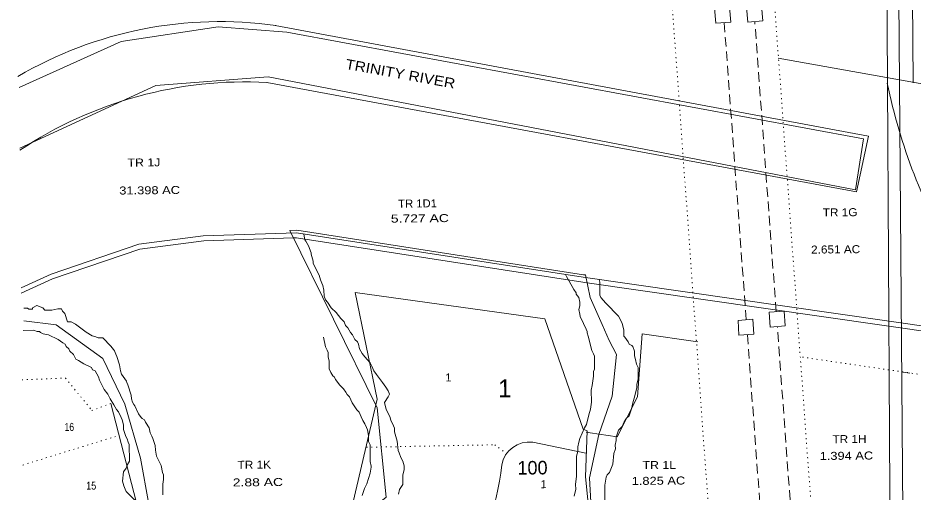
# Model space of a CAD drawing. Extents: x 2356373 to 2371954, y 6966197 to 6989612.
# Drawn here: x 2360014 to 2361802, y 6970054 to 6971002 of the extents above; entities that cross this region are included whole.
import ezdxf

# ---------------------------------------------------------------- set-up
doc = ezdxf.new("R2010")
doc.units = 0
doc.header["$LTSCALE"] = 6.4
doc.linetypes.add('DOTTED', pattern=[1.5, 0.3, -1.2])
doc.linetypes.add('MEDIUM_DASHED', pattern=[4.5, 3, -1.5])
for name, color, linetype in [('10', 7, 'Continuous'), ('11', 7, 'Continuous'), ('22', 7, 'Continuous')]:
    doc.layers.add(name, color=color, linetype=linetype)
for name, color, linetype, lineweight in [('12', 7, 'Continuous', 13), ('15', 7, 'Continuous', 13), ('16', 7, 'DOTTED', 13), ('19', 7, 'Continuous', 13), ('23', 7, 'Continuous', 13), ('4', 7, 'Continuous', 13), ('5', 7, 'DOTTED', 13), ('6', 7, 'DOTTED', 13), ('7', 7, 'Continuous', 13), ('8', 7, 'Continuous', 13)]:
    doc.layers.add(name, color=color, linetype=linetype, lineweight=lineweight)

msp = doc.modelspace()

# ---------------------------------------------------------------- linework, layer by layer
at = {"layer": '15'}
for p, q in [((2361802.174, 6970872.225), (2361797.483, 6971655.071)), ((2361042.439, 6970153.453), (2361148.623, 6970131.802))]:
    msp.add_line(p, q, dxfattribs=at)
for points in [[(2361738.823, 6972843.476), (2361751.197, 6970871.325), (2361761.412, 6969118.792)], [(2360511.51, 6970872.945), (2361689.347, 6970654.176), (2361713.245, 6970765.68), (2360528.392, 6970986.48)]]:
    msp.add_lwpolyline(points, dxfattribs=at)
for centre, radius, start, end in [((2360417.148, 6970199.997), 794.433, 81.88238, 120.47566), ((2360469.516, 6970059.349), 814.671, 87.01949, 123.65656), ((2362878.61, 6971103.94), 1151.664, 191.65156, 210.55236), ((2361034.975, 6970099.094), 54.829, 82.19276, 170.49276), ((2360374.316, 6970184.08), 611.447, 303.69276, 352.87276)]:
    msp.add_arc(centre, radius, start, end, dxfattribs=at)
at = {"layer": '16', "linetype": 'Continuous'}
msp.add_lwpolyline([(2360199.899, 6970231.254), (2360287.197, 6969893.303), (2360379.713, 6969838.225), (2360667.407, 6969963.218), (2360731.677, 6970239.377), (2360687.593, 6970452.786), (2361067.007, 6970400.229), (2361143.158, 6970179.336), (2361151.185, 6970176.316), (2361148.09, 6970084.311), (2361173.615, 6969826.629), (2361271.534, 6969628.544), (2361433.018, 6969473.171)], dxfattribs=at)
at = {"layer": '16'}
msp.add_lwpolyline([(2360022.485, 6970278.299), (2360109.428, 6970281.752), (2360162.05, 6970216.886), (2360199.899, 6970231.254)], dxfattribs=at)
at = {"layer": '23'}
for points in [[(2360026.322, 6970396.504), (2360090.389, 6970387.937), (2360184.019, 6970321.174), (2360227.91, 6970229.331), (2360258.957, 6970121.964), (2360275.857, 6970029.854), (2360304.087, 6969903.966), (2360388.388, 6969871.002), (2360563.142, 6969891.213), (2360749.595, 6970043.704), (2360731.849, 6970221.983), (2360557.41, 6970576.775), (2360571.401, 6970577.212), (2361144.12, 6970488.463), (2361148.124, 6970487.902)], [(2361148.124, 6970487.902), (2361157.563, 6970442.906), (2361181.088, 6970388.952), (2361195.395, 6970357.201), (2361209.672, 6970328.649), (2361201.489, 6970245.691), (2361174.252, 6970168.844), (2361156.104, 6970082.59), (2361162.295, 6969961.381), (2361171.728, 6969916.886), (2361200.971, 6969789.607), (2361296.505, 6969630.989), (2361412.003, 6969475.265), (2361553.897, 6969380.384), (2361655.447, 6969321.698), (2361736.506, 6969313.397), (2361856.463, 6969314.575)]]:
    msp.add_lwpolyline(points, dxfattribs=at)
at = {"layer": '4'}
msp.add_line((2361782.378, 6969935.981), (2361759.816, 6972843.683), dxfattribs=at)
at = {"layer": '5'}
for p, q in [((2361243.154, 6972110.703), (2361433.018, 6969473.171)), ((2361886.982, 6970278.716), (2361578.62, 6970323.975))]:
    msp.add_line(p, q, dxfattribs=at)
at = {"layer": '5', "linetype": 'Continuous'}
for p, q in [((2361532.763, 6970921.465), (2362277.875, 6970787.821)), ((2361795.878, 6970291.918), (2361781.861, 6970293.88)), ((2361149.214, 6970173.397), (2361157.223, 6970172.376))]:
    msp.add_line(p, q, dxfattribs=at)
at = {"layer": '5'}
msp.add_lwpolyline([(2361438.68, 6972560.804), (2361447.153, 6972105.409), (2361678.26, 6968932.926)], dxfattribs=at)
at = {"layer": '5', "linetype": 'Continuous'}
for points in [[(2360020.783, 6970451.535), (2360083.482, 6970480.345), (2360257.856, 6970539.541), (2360385.654, 6970556.493), (2360564.552, 6970562.049)], [(2360564.552, 6970562.049), (2360570.547, 6970562.207), (2361142.266, 6970473.649), (2361146.271, 6970473.087)], [(2361146.271, 6970473.087), (2361860.09, 6970370.228), (2361865.672, 6970412.771), (2361948.776, 6970399.791)], [(2361157.223, 6970172.376), (2361211.286, 6970164.409), (2361251.491, 6970244.283), (2361261.25, 6970370.144), (2361372.381, 6970353.942)]]:
    msp.add_lwpolyline(points, dxfattribs=at)
at = {"layer": '6'}
msp.add_line((2360024.158, 6970107.961), (2360214.529, 6970166.715), dxfattribs=at)
msp.add_lwpolyline([(2360710.625, 6970143.494), (2360966.509, 6970148.408), (2360988.664, 6970132.029)], dxfattribs=at)
at = {"layer": '7', "linetype": 'MEDIUM_DASHED'}
for p, q in [((2361425.095, 6970992.288), (2361468.918, 6970398.377)), ((2361528.743, 6970414.561), (2361486.055, 6970994.687)), ((2361571.403, 6969837.335), (2361531.036, 6970384.691)), ((2361471.21, 6970368.508), (2361511.553, 6969823.65))]:
    msp.add_line(p, q, dxfattribs=at)
at = {"layer": '7'}
for points in [[(2361405.817, 6971020.991), (2361408.111, 6970991.121), (2361438.081, 6970993.316), (2361435.788, 6971023.286)], [(2361502.039, 6970995.844), (2361499.745, 6971025.813), (2361469.776, 6971023.52), (2361472.069, 6970993.649)], [(2361547.02, 6970385.949), (2361544.727, 6970415.818), (2361514.757, 6970413.624), (2361517.049, 6970383.654)], [(2361452.934, 6970397.22), (2361454.227, 6970367.341), (2361484.198, 6970369.536), (2361481.905, 6970399.405)]]:
    msp.add_lwpolyline(points, close=True, dxfattribs=at)
at = {"layer": '8'}
for points in [[(2360017.932, 6970741.73), (2360289.631, 6970866.766), (2360514.401, 6970884.171), (2361687.308, 6970658.154), (2361703.305, 6970759.785), (2360551.513, 6970973.511), (2360414.446, 6970984.062), (2360220.784, 6970954.866), (2360016.746, 6970862.586)], [(2361949.679, 6970409.699), (2361857.561, 6970424.189), (2361851.981, 6970381.546), (2361143.168, 6970483.555), (2360570.45, 6970572.204), (2360384.556, 6970566.478), (2360255.759, 6970549.318), (2360080.392, 6970489.611), (2360020.675, 6970462.532)], [(2360774.527, 6970049.948), (2360776.434, 6970059.265), (2360783.341, 6970068.73), (2360783.156, 6970087.523), (2360786.038, 6970099.349), (2360785.97, 6970106.346), (2360782.878, 6970115.712), (2360778.81, 6970122.771), (2360775.719, 6970132.138), (2360773.674, 6970136.816), (2360771.489, 6970155.59), (2360766.307, 6970174.335), (2360766.237, 6970181.332), (2360764.193, 6970186.01), (2360759.08, 6970197.658), (2360757.011, 6970204.736), (2360749.874, 6970218.761), (2360746.738, 6970232.828), (2360753.621, 6970244.592), (2360756.574, 6970249.319), (2360753.505, 6970256.387), (2360749.437, 6970263.345), (2360742.347, 6970272.673), (2360730.191, 6970289.049), (2360725.122, 6970296.097), (2360721.031, 6970305.455), (2360717.963, 6970312.422), (2360706.852, 6970324.109), (2360701.784, 6970331.059), (2360696.694, 6970340.406), (2360694.602, 6970349.783), (2360692.557, 6970354.461), (2360687.514, 6970359.111), (2360682.422, 6970368.458), (2360678.377, 6970373.118), (2360673.287, 6970382.465), (2360668.244, 6970387.114), (2360666.173, 6970394.192), (2360659.107, 6970401.121), (2360649.994, 6970412.828), (2360639.906, 6970422.127), (2360632.794, 6970433.852), (2360628.748, 6970438.512), (2360625.68, 6970445.481), (2360625.564, 6970457.277), (2360623.474, 6970466.654), (2360621.427, 6970471.33), (2360618.36, 6970478.3), (2360616.268, 6970487.677), (2360604.042, 6970511.05), (2360603.996, 6970515.748), (2360599.859, 6970529.804), (2360599.835, 6970532.204), (2360594.699, 6970546.249), (2360589.609, 6970555.596), (2360587.587, 6970557.877), (2360585.471, 6970569.651), (2360584.467, 6970570.042)], [(2361108.123, 6970489.109), (2361110.166, 6970484.73), (2361115.255, 6970475.383), (2361124.415, 6970458.977), (2361129.483, 6970452.028), (2361129.505, 6970449.63), (2361134.571, 6970442.681), (2361136.664, 6970433.303), (2361136.734, 6970426.207), (2361134.803, 6970419.188), (2361136.894, 6970409.812), (2361136.942, 6970405.114), (2361144.076, 6970391.088), (2361149.19, 6970379.341), (2361151.236, 6970374.663), (2361151.259, 6970372.363), (2361153.328, 6970365.286), (2361160.602, 6970337.165), (2361163.67, 6970330.197), (2361165.714, 6970325.519), (2361165.968, 6970299.728), (2361164.016, 6970295.01), (2361164.108, 6970285.613), (2361161.294, 6970266.791), (2361159.387, 6970257.375), (2361159.616, 6970233.883), (2361157.756, 6970219.769), (2361154.871, 6970208.043), (2361150.058, 6970189.201), (2361146.128, 6970182.164), (2361136.34, 6970160.873), (2361134.41, 6970153.856), (2361132.502, 6970144.44), (2361132.595, 6970135.044), (2361129.689, 6970125.618), (2361130.081, 6970085.733), (2361128.244, 6970069.218), (2361128.336, 6970059.823), (2361125.475, 6970045.798)], [(2361224.302, 6970365.883), (2361224.188, 6970377.679), (2361221.05, 6970391.743), (2361213.914, 6970405.77), (2361188.669, 6970431.415), (2361178.557, 6970443.013), (2361176.512, 6970447.692), (2361176.258, 6970473.583), (2361175.205, 6970478.969)], [(2360240.798, 6970240.354), (2360240.729, 6970247.45), (2360233.524, 6970268.474), (2360231.479, 6970273.154), (2360231.456, 6970275.553), (2360224.365, 6970284.88), (2360221.32, 6970289.548), (2360219.252, 6970296.526), (2360217.138, 6970308.303), (2360211.978, 6970324.648), (2360209.933, 6970329.327), (2360206.864, 6970336.394), (2360204.842, 6970338.674), (2360199.774, 6970345.722), (2360183.619, 6970362.059), (2360174.621, 6970361.971), (2360169.6, 6970364.221), (2360162.58, 6970366.55), (2360150.515, 6970373.531), (2360129.362, 6970389.719), (2360120.319, 6970394.33), (2360113.32, 6970394.36), (2360108.16, 6970410.705), (2360103.116, 6970415.354), (2360101.071, 6970420.032), (2360094.074, 6970419.965), (2360082.101, 6970417.548), (2360068.106, 6970417.409), (2360064.06, 6970422.068), (2360052.019, 6970426.648), (2360043.067, 6970421.964), (2360043.09, 6970419.563), (2360036.094, 6970419.494), (2360033.071, 6970421.865), (2360026.074, 6970421.795)], [(2360024.512, 6970377.192), (2360045.505, 6970377.299), (2360052.525, 6970375.068), (2360057.524, 6970375.116), (2360059.547, 6970372.738), (2360064.569, 6970370.388), (2360075.587, 6970368.197), (2360094.672, 6970358.986), (2360103.739, 6970351.977), (2360108.761, 6970349.628), (2360110.806, 6970344.947), (2360115.851, 6970340.299), (2360117.895, 6970335.62), (2360124.962, 6970328.692), (2360130.052, 6970319.344), (2360135.074, 6970316.995), (2360146.14, 6970310.004), (2360161.203, 6970303.154), (2360163.248, 6970298.476), (2360168.271, 6970296.125), (2360175.382, 6970284.498), (2360177.452, 6970277.421), (2360186.632, 6970258.717), (2360193.722, 6970249.389), (2360198.813, 6970240.041), (2360205.926, 6970228.315), (2360211.016, 6970218.967), (2360215.062, 6970214.307), (2360220.176, 6970202.66), (2360222.22, 6970197.983), (2360225.312, 6970188.616), (2360225.403, 6970179.219), (2360229.541, 6970165.163), (2360232.585, 6970160.494), (2360234.653, 6970153.416), (2360236.7, 6970148.737), (2360237.022, 6970115.948), (2360233.094, 6970108.813), (2360230.163, 6970101.786), (2360225.235, 6970094.64), (2360223.419, 6970075.926), (2360225.51, 6970066.55), (2360228.579, 6970059.482), (2360230.625, 6970054.803), (2360263.935, 6970022.24)], [(2361186.591, 6970032.202), (2361186.246, 6970067.389), (2361189.085, 6970083.813), (2361191.036, 6970088.53), (2361195.989, 6970093.277), (2361199.896, 6970102.713), (2361202.824, 6970109.84), (2361204.616, 6970130.952), (2361207.523, 6970140.378), (2361207.453, 6970147.376), (2361209.362, 6970156.792), (2361209.292, 6970163.889), (2361214.152, 6970177.934), (2361221.079, 6970185.101), (2361224.987, 6970194.536), (2361229.915, 6970201.581), (2361234.868, 6970206.329), (2361239.728, 6970220.474), (2361241.634, 6970229.89), (2361243.565, 6970236.907), (2361246.471, 6970246.332), (2361250.31, 6970262.766), (2361250.238, 6970269.864), (2361253.146, 6970279.289), (2361252.916, 6970302.781), (2361249.848, 6970309.749), (2361247.757, 6970319.126), (2361245.687, 6970326.203), (2361245.595, 6970335.6), (2361242.503, 6970344.967), (2361240.482, 6970347.247), (2361235.46, 6970349.597), (2361233.415, 6970354.276), (2361226.325, 6970363.603), (2361224.302, 6970365.883)], [(2360624.489, 6970363.292), (2360628.671, 6970344.537), (2360631.74, 6970337.568), (2360633.785, 6970332.89), (2360633.877, 6970323.494), (2360635.946, 6970316.416), (2360636.107, 6970300.021), (2360639.176, 6970292.954), (2360643.243, 6970285.996), (2360646.265, 6970283.626), (2360648.311, 6970278.946), (2360657.422, 6970267.34), (2360664.49, 6970260.311), (2360669.557, 6970253.362), (2360671.602, 6970248.685), (2360676.646, 6970244.035), (2360681.76, 6970232.288), (2360690.896, 6970218.282), (2360695.939, 6970213.633), (2360700.031, 6970204.275), (2360703.099, 6970197.208), (2360707.167, 6970190.249), (2360710.236, 6970183.181), (2360712.28, 6970178.503), (2360714.395, 6970166.826), (2360714.51, 6970155.03), (2360717.579, 6970148.063), (2360717.901, 6970115.174), (2360719.993, 6970105.798), (2360720.016, 6970103.498), (2360718.133, 6970091.683), (2360711.343, 6970070.521), (2360706.437, 6970061.076), (2360701.576, 6970046.932)], [(2360303.668, 6970048.322), (2360303.46, 6970069.515), (2360305.367, 6970078.931), (2360305.275, 6970088.328), (2360303.231, 6970093.007), (2360300.092, 6970107.071), (2360290.912, 6970125.776), (2360288.797, 6970137.453), (2360288.705, 6970146.849), (2360283.569, 6970160.894), (2360281.523, 6970165.574), (2360278.454, 6970172.641), (2360276.363, 6970182.019), (2360269.251, 6970193.647), (2360267.205, 6970198.325), (2360262.182, 6970200.673), (2360260.162, 6970202.953), (2360255.093, 6970210.003), (2360247.934, 6970226.327), (2360245.913, 6970228.707), (2360242.867, 6970233.376), (2360240.798, 6970240.354)]]:
    msp.add_lwpolyline(points, dxfattribs=at)

# ---------------------------------------------------------------- texts
at = {"layer": '10'}
for s, width, p in [('TR 1J', 1.15, (2360233.24, 6970704.555)), ('TR 1D1', 1.05, (2360773.902, 6970622.489)), ('TR 1G', 1.1, (2361621.849, 6970604.825)), ('TR 1H', 1.1, (2361641.297, 6970151.536)), ('TR 1K', 1.1, (2360453.118, 6970100.277)), ('TR 1L', 1.15, (2361261.91, 6970099.624))]:
    msp.add_text(s, height=15.99, rotation=0.563, dxfattribs=dict(at, width=width)).set_placement(p)
at = {"layer": '11'}
for s, width, p in [('31.398 AC', 1.2, (2360216.793, 6970648.708)), ('5.727 AC', 1.3, (2360759.201, 6970592.553)), ('2.651 AC', 1.1, (2361598.584, 6970530.616)), ('1.394 AC', 1.2, (2361615.634, 6970117.994)), ('2.88 AC', 1.3, (2360443.467, 6970065.092)), ('1.825 AC', 1.2, (2361240.225, 6970068.021))]:
    msp.add_text(s, height=15.99, rotation=0.563, dxfattribs=dict(at, width=width)).set_placement(p)
at = {"layer": '12'}
for p in [(2360868.291, 6970275.009), (2361058.337, 6970061.634)]:
    msp.add_text('1', height=15.99, rotation=0.563, dxfattribs=at).set_placement(p)
for s, width, p in [('16', 0.8, (2360107.467, 6970175.961)), ('15', 0.85, (2360150.609, 6970058.617))]:
    msp.add_text(s, height=15.99, rotation=0.563, dxfattribs=dict(at, width=width)).set_placement(p)
at = {"layer": '19', "width": 1.15}
msp.add_text('TRINITY RIVER', height=19.99, rotation=349.695, dxfattribs=at).set_placement((2360667.202, 6970900.268))
at = {"layer": '22'}
for s, height, p in [('1', 35.99, (2360973.577, 6970243.052)), ('100', 26.99, (2361012.082, 6970088.772))]:
    msp.add_text(s, height=height, rotation=0.563, dxfattribs=at).set_placement(p)

doc.saveas('drawing.dxf')
